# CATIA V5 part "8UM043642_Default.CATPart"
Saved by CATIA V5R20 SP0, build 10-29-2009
Part number: 8UM043642_Default
Revision: ANY
Definition: UNKNOWN
Nomenclature: 8UM043642_Default
Source: Unknown
Bounding box of the stored display mesh (mm): x -47.308 to -11.308, y 0 to 28, z -41.652 to 0.348
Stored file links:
  C:\Users\Utente\Desktop\IO LAVORO\3D X SITO CF\X SITO\3D files UM\UM043642 PRODUCT\8UM043642_Default.CATPart
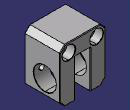
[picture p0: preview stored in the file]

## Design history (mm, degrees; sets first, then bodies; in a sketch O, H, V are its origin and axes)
Body1 "Taladro roscado M51" (main body)
  Solid1: solid without history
